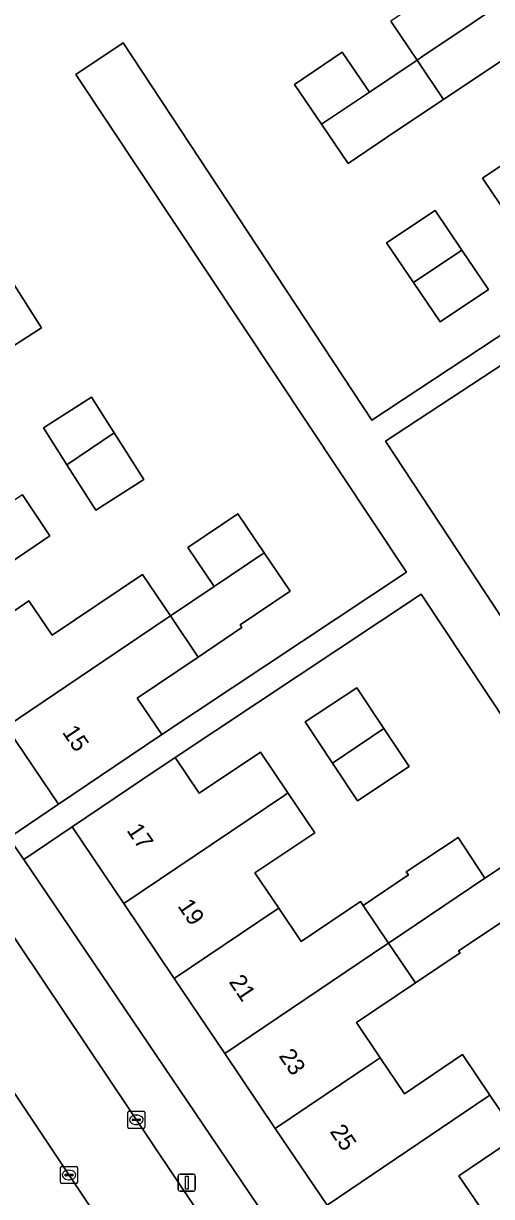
# Model space of a CAD drawing. Extents: x 158352 to 159489, y 383828 to 384603.
# Drawn here: x 158835 to 158862.4, y 384098.8 to 384167.6 of the extents above; entities that cross this region are included whole.
import ezdxf

# ---------------------------------------------------------------- set-up
doc = ezdxf.new("R2010")
doc.units = 0
for name, color, linetype in [('IMGEO_Erf', 7, 'Continuous'), ('IMGEO_Kolk', 7, 'Continuous'), ('IMGEO_Lichtmast', 7, 'Continuous'), ('IMGEO_Pand', 7, 'Continuous'), ('IMGEO_Pand_nummerreeks', 7, 'Continuous'), ('IMGEO_Parkeervlak_open', 7, 'Continuous'), ('IMGEO_Rijbaan_lokaal_open', 7, 'Continuous'), ('IMGEO_Voetpad_open', 7, 'Continuous')]:
    doc.layers.add(name, color=color, linetype=linetype)

msp = doc.modelspace()

# ---------------------------------------------------------------- linework, layer by layer
at = {"layer": 'IMGEO_Erf'}
for points in [[(158863.115, 384165.499), (158859.582, 384163.125), (158856.783, 384161.273), (158853.989, 384159.375), (158852.425, 384161.684), (158850.852, 384164.006), (158853.646, 384165.904), (158855.229, 384163.567), (158858.024, 384165.444), (158856.487, 384167.731)], [(158834.451, 384133.175), (158835.28, 384133.733), (158836.639, 384131.715), (158841.93, 384135.281), (158843.57, 384132.847), (158846.135, 384134.575), (158844.593, 384136.857), (158847.52, 384138.833), (158849.063, 384136.548), (158850.584, 384134.295), (158847.658, 384132.319), (158847.76, 384132.168), (158845.193, 384130.438), (158841.625, 384128.033), (158843.069, 384125.891), (158857.411, 384135.409), (158838.032, 384164.608), (158840.811, 384166.452), (158855.372, 384144.324), (158869.956, 384153.946)], [(158863.444, 384156.173), (158861.868, 384158.518), (158865.324, 384160.84)], [(158870.79, 384152.704), (158856.183, 384143.092), (158874.109, 384115.848)], [(158834.895, 384139.947), (158836.511, 384137.55), (158833.068, 384135.23)], [(158872.435, 384112.771), (158858.266, 384134.119), (158843.849, 384124.551), (158845.264, 384122.453), (158848.842, 384124.865), (158850.457, 384122.469), (158852.026, 384120.142), (158848.525, 384117.783), (158849.918, 384115.716), (158851.232, 384113.767), (158854.709, 384116.111), (158854.866, 384115.878), (158857.517, 384117.665), (158857.395, 384117.848), (158860.426, 384119.856), (158862.005, 384117.473), (158864.326, 384119.01)], [(158865.811, 384116.767), (158860.459, 384113.222), (158860.546, 384113.09), (158857.933, 384111.329), (158854.482, 384109.003), (158855.868, 384106.946), (158857.293, 384104.833), (158860.694, 384107.127), (158862.299, 384104.746), (158863.921, 384102.34), (158860.483, 384100.022), (158861.759, 384098.128)]]:
    msp.add_lwpolyline(points, dxfattribs=at)
for points in [[(158856.242, 384154.72), (158859.084, 384156.62), (158860.655, 384154.301), (158862.221, 384151.989), (158859.379, 384150.089), (158857.817, 384152.394)], [(158836.022, 384149.748), (158833.2, 384147.953), (158831.509, 384150.611), (158830.125, 384152.788), (158832.947, 384154.583), (158834.284, 384152.481)], [(158840.284, 384143.578), (158842.022, 384140.845), (158839.2, 384139.05), (158837.509, 384141.708), (158836.125, 384143.885), (158838.947, 384145.68)], [(158854.535, 384122.009), (158853.066, 384124.227), (158851.471, 384126.635), (158854.502, 384128.643), (158856.082, 384126.259), (158857.567, 384124.017)], [(158834.035, 384126.218), (158831.124, 384124.256), (158834.108, 384119.846), (158837.007, 384121.807)], [(158849.719, 384102.801), (158846.757, 384107.195), (158843.795, 384111.589), (158840.833, 384115.982), (158837.804, 384120.475), (158834.976, 384118.562), (158856.419, 384086.867), (158865.594, 384081.861), (158868.026, 384086.341), (158863.257, 384088.93), (158862.58, 384087.684), (158857.686, 384090.341), (158857.879, 384090.697), (158852.748, 384098.308)]]:
    msp.add_lwpolyline(points, close=True, dxfattribs=at)
at = {"layer": 'IMGEO_Kolk'}
for p, q in [((158841.075, 384102.877), (158841.075, 384103.729)), ((158841.15, 384103.803), (158842.002, 384103.803)), ((158841.563, 384103.583), (158841.588, 384103.583)), ((158842.076, 384103.729), (158842.076, 384102.877)), ((158841.334, 384103.297), (158841.334, 384103.309)), ((158841.772, 384103.26), (158841.374, 384103.26)), ((158841.377, 384103.346), (158841.775, 384103.346)), ((158841.586, 384103.023), (158841.561, 384103.023)), ((158841.818, 384103.309), (158841.818, 384103.297)), ((158842.002, 384102.803), (158841.15, 384102.803)), ((158837.125, 384099.645), (158837.125, 384100.497)), ((158837.2, 384100.571), (158838.052, 384100.571)), ((158837.613, 384100.351), (158837.638, 384100.351)), ((158838.126, 384100.497), (158838.126, 384099.645)), ((158838.052, 384099.571), (158837.2, 384099.571)), ((158837.384, 384100.065), (158837.384, 384100.077)), ((158837.822, 384100.028), (158837.424, 384100.028)), ((158837.427, 384100.114), (158837.825, 384100.114)), ((158837.636, 384099.791), (158837.611, 384099.791)), ((158837.868, 384100.077), (158837.868, 384100.065))]:
    msp.add_line(p, q, dxfattribs=at)
for points in [[(158841.075, 384102.877), (158841.075, 384103.729)], [(158841.15, 384103.803), (158842.002, 384103.803)], [(158842.076, 384103.729), (158842.076, 384102.877)], [(158842.002, 384102.803), (158841.15, 384102.803)], [(158837.125, 384099.645), (158837.125, 384100.497)], [(158837.2, 384100.571), (158838.052, 384100.571)], [(158838.126, 384100.497), (158838.126, 384099.645)], [(158838.052, 384099.571), (158837.2, 384099.571)]]:
    msp.add_lwpolyline(points, dxfattribs=at)
for centre, radius, start, end in [((158841.152, 384103.727), 0.0765, 91.55205, 178.44795), ((158841.152, 384103.727), 0.0765, 91.55205, 178.44795), ((158842, 384103.727), 0.0765, 1.55205, 88.44795), ((158842, 384103.727), 0.0765, 1.55205, 88.44795), ((158841.152, 384102.879), 0.0765, 181.55205, 268.44795), ((158841.152, 384102.879), 0.0765, 181.55205, 268.44795), ((158841.374, 384103.306), 0.0403, 85.87752, 175.75265), ((158841.371, 384103.296), 0.0366, 178.93798, 274.71019), ((158841.775, 384103.303), 0.043, 264.86636, 352.45326), ((158841.779, 384103.308), 0.0386, 1.73085, 96.63898), ((158842, 384102.879), 0.0765, 271.55205, 358.44795), ((158842, 384102.879), 0.0765, 271.55205, 358.44795), ((158837.202, 384100.495), 0.0765, 91.55205, 178.44795), ((158837.202, 384100.495), 0.0765, 91.55205, 178.44795), ((158838.05, 384100.495), 0.0765, 1.55205, 88.44795), ((158838.05, 384100.495), 0.0765, 1.55205, 88.44795), ((158837.202, 384099.647), 0.0765, 181.55205, 268.44795), ((158837.202, 384099.647), 0.0765, 181.55205, 268.44795), ((158837.424, 384100.074), 0.0403, 85.87752, 175.75265), ((158837.421, 384100.064), 0.0366, 178.93798, 274.71019), ((158837.825, 384100.071), 0.043, 264.86636, 352.45326), ((158837.829, 384100.076), 0.0386, 1.73085, 96.63898), ((158838.05, 384099.647), 0.0765, 271.55205, 358.44795), ((158838.05, 384099.647), 0.0765, 271.55205, 358.44795)]:
    msp.add_arc(centre, radius, start, end, dxfattribs=at)
for centre, major_axis, ratio, start_param, end_param in [((158841.562, 384103.303), (-0.387, 0.002), 0.722429, 4.712389, 7.853982), ((158841.587, 384103.303), (-0.39, 0.002), 0.717154, 1.570796, 4.712389), ((158837.612, 384100.071), (-0.387, 0.002), 0.722429, 4.712389, 7.853982), ((158837.637, 384100.071), (-0.39, 0.002), 0.717154, 1.570796, 4.712389)]:
    msp.add_ellipse(centre, major_axis=major_axis, ratio=ratio, start_param=start_param, end_param=end_param, dxfattribs=at)
at = {"layer": 'IMGEO_Lichtmast'}
for p, q in [((158844.033, 384099.218), (158844.033, 384100.018)), ((158844.033, 384100.018), (158844.033, 384099.218)), ((158844.133, 384100.118), (158844.923, 384100.118)), ((158844.923, 384100.118), (158844.133, 384100.118)), ((158845.023, 384100.018), (158845.023, 384099.218)), ((158845.023, 384099.218), (158845.023, 384100.018)), ((158844.923, 384099.118), (158844.133, 384099.118)), ((158844.133, 384099.118), (158844.923, 384099.118))]:
    msp.add_line(p, q, dxfattribs=at)
msp.add_lwpolyline([(158844.453, 384099.993), (158844.603, 384099.993), (158844.603, 384099.243), (158844.453, 384099.243), (158844.453, 384099.993)], dxfattribs=at)
for centre, start, end in [((158844.133, 384100.018), 90, 180), ((158844.133, 384100.018), 90, 180), ((158844.923, 384100.018), 0, 90), ((158844.923, 384100.018), 360, 90), ((158844.133, 384099.218), 180, 270), ((158844.133, 384099.218), 180, 270), ((158844.923, 384099.218), 270, 0), ((158844.923, 384099.218), 270, 0)]:
    msp.add_arc(centre, 0.1, start, end, dxfattribs=at)
at = {"layer": 'IMGEO_Pand'}
for points in [[(158867.501, 384171.811), (158865.246, 384175.168), (158864.588, 384176.147), (158864.513, 384176.259), (158858.517, 384172.232), (158858.716, 384171.937), (158858.956, 384171.581), (158859.97, 384170.072), (158856.487, 384167.731), (158858.024, 384165.444), (158858.355, 384165.667)], [(158858.024, 384165.444), (158859.582, 384163.125), (158863.115, 384165.499), (158864.381, 384163.616), (158863.746, 384163.189), (158863.911, 384162.943), (158864.307, 384163.209), (158870.778, 384167.555), (158870.648, 384167.748), (158870.361, 384167.555), (158867.501, 384171.811), (158858.355, 384165.667)], [(158873.028, 384162.611), (158873.766, 384163.107), (158870.778, 384167.555), (158864.307, 384163.209), (158863.911, 384162.943), (158865.324, 384160.84), (158861.868, 384158.518), (158863.444, 384156.173), (158863.678, 384156.331)], [(158855.229, 384163.567), (158853.646, 384165.904), (158850.852, 384164.006), (158852.425, 384161.684)], [(158859.582, 384163.125), (158858.024, 384165.444), (158855.229, 384163.567), (158852.425, 384161.684), (158853.989, 384159.375), (158856.783, 384161.273)], [(158857.817, 384152.394), (158860.655, 384154.301), (158859.084, 384156.62), (158856.242, 384154.72)], [(158857.817, 384152.394), (158859.379, 384150.089), (158862.221, 384151.989), (158860.655, 384154.301)], [(158831.509, 384150.611), (158833.2, 384147.953), (158836.022, 384149.748), (158834.284, 384152.481)], [(158837.509, 384141.708), (158840.284, 384143.578), (158838.947, 384145.68), (158836.125, 384143.885)], [(158837.509, 384141.708), (158839.2, 384139.05), (158842.022, 384140.845), (158840.284, 384143.578)], [(158834.895, 384139.947), (158834.692, 384139.81), (158825.322, 384133.496), (158827.539, 384130.206), (158828.228, 384129.183), (158828.322, 384129.044), (158834.451, 384133.175), (158834.279, 384133.431), (158833.068, 384135.23), (158836.511, 384137.55)], [(158846.135, 384134.575), (158849.063, 384136.548), (158847.52, 384138.833), (158844.593, 384136.857)], [(158849.063, 384136.548), (158846.135, 384134.575), (158843.57, 384132.847), (158845.193, 384130.438), (158847.76, 384132.168), (158847.658, 384132.319), (158850.584, 384134.295)], [(158843.29, 384132.658), (158843.57, 384132.847), (158841.93, 384135.281), (158836.639, 384131.715), (158835.28, 384133.733), (158834.451, 384133.175), (158828.322, 384129.044), (158828.03, 384128.847), (158831.03, 384124.396)], [(158843.57, 384132.847), (158843.29, 384132.658), (158831.03, 384124.396), (158831.124, 384124.256), (158834.035, 384126.218), (158837.007, 384121.807), (158841.154, 384124.601), (158843.069, 384125.891), (158841.625, 384128.033), (158845.193, 384130.438)], [(158853.066, 384124.227), (158856.082, 384126.259), (158854.502, 384128.643), (158851.471, 384126.635)], [(158853.066, 384124.227), (158854.535, 384122.009), (158857.567, 384124.017), (158856.082, 384126.259)], [(158840.833, 384115.982), (158850.213, 384122.304), (158850.457, 384122.469), (158848.842, 384124.865), (158845.264, 384122.453), (158843.849, 384124.551), (158841.95, 384123.271), (158837.804, 384120.475)], [(158849.918, 384115.716), (158848.525, 384117.783), (158852.026, 384120.142), (158850.457, 384122.469), (158850.213, 384122.304), (158840.833, 384115.982), (158843.795, 384111.589), (158849.704, 384115.572)], [(158854.866, 384115.878), (158856.357, 384113.666), (158862.005, 384117.473), (158860.426, 384119.856), (158857.395, 384117.848), (158857.517, 384117.665)], [(158862.005, 384117.473), (158856.357, 384113.666), (158857.933, 384111.329), (158860.546, 384113.09), (158860.459, 384113.222), (158865.811, 384116.767), (158864.326, 384119.01)], [(158856.2, 384113.56), (158856.357, 384113.666), (158854.866, 384115.878), (158854.709, 384116.111), (158851.232, 384113.767), (158849.918, 384115.716), (158849.704, 384115.572), (158843.795, 384111.589), (158846.757, 384107.195)], [(158849.719, 384102.801), (158855.521, 384106.712), (158855.868, 384106.946), (158854.482, 384109.003), (158857.933, 384111.329), (158856.357, 384113.666), (158856.2, 384113.56), (158846.757, 384107.195)], [(158852.748, 384098.308), (158862.12, 384104.626), (158862.299, 384104.746), (158860.694, 384107.127), (158857.293, 384104.833), (158855.868, 384106.946), (158855.521, 384106.712), (158849.719, 384102.801)], [(158857.879, 384090.697), (158861.648, 384097.772), (158861.946, 384098.047), (158861.759, 384098.128), (158860.483, 384100.022), (158863.921, 384102.34), (158862.299, 384104.746), (158862.12, 384104.626), (158852.748, 384098.308)]]:
    msp.add_lwpolyline(points, close=True, dxfattribs=at)
at = {"layer": 'IMGEO_Parkeervlak_open'}
msp.add_lwpolyline([(158839.9, 384096.663), (158827.035, 384115.958)], dxfattribs=at)
at = {"layer": 'IMGEO_Rijbaan_lokaal_open'}
for points in [[(158829.599, 384121.155), (158826.493, 384119.15), (158825.384, 384118.435), (158827.035, 384115.958), (158839.9, 384096.663), (158840.225, 384096.175)], [(158846.369, 384096.156), (158829.599, 384121.155)]]:
    msp.add_lwpolyline(points, dxfattribs=at)
at = {"layer": 'IMGEO_Voetpad_open'}
for points in [[(158869.956, 384153.946), (158855.372, 384144.324), (158840.811, 384166.452), (158838.032, 384164.608), (158857.411, 384135.409), (158843.069, 384125.891), (158841.154, 384124.601), (158837.007, 384121.807), (158834.108, 384119.846), (158834.976, 384118.562), (158837.804, 384120.475), (158841.95, 384123.271), (158843.849, 384124.551), (158858.266, 384134.119), (158872.435, 384112.771)], [(158874.109, 384115.848), (158856.183, 384143.092), (158870.79, 384152.704)], [(158829.599, 384121.155), (158846.369, 384096.156)], [(158856.419, 384086.867), (158834.976, 384118.562), (158834.108, 384119.846)]]:
    msp.add_lwpolyline(points, dxfattribs=at)

# ---------------------------------------------------------------- texts
at = {"layer": 'IMGEO_Pand_nummerreeks'}
for s, rotation, p in [('15', 303.97091, (158837.2, 384126.03)), ('17', 303.98609, (158840.976, 384120.276)), ('19', 303.98609, (158843.965, 384115.843)), ('21', 303.98765, (158846.968, 384111.392)), ('23', 303.98609, (158849.892, 384107.052)), ('25', 303.98609, (158852.881, 384102.619))]:
    msp.add_text(s, height=1, rotation=rotation, dxfattribs=at).set_placement(p)

doc.saveas('drawing.dxf')
